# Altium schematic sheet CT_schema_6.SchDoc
size 368 x 245 mm
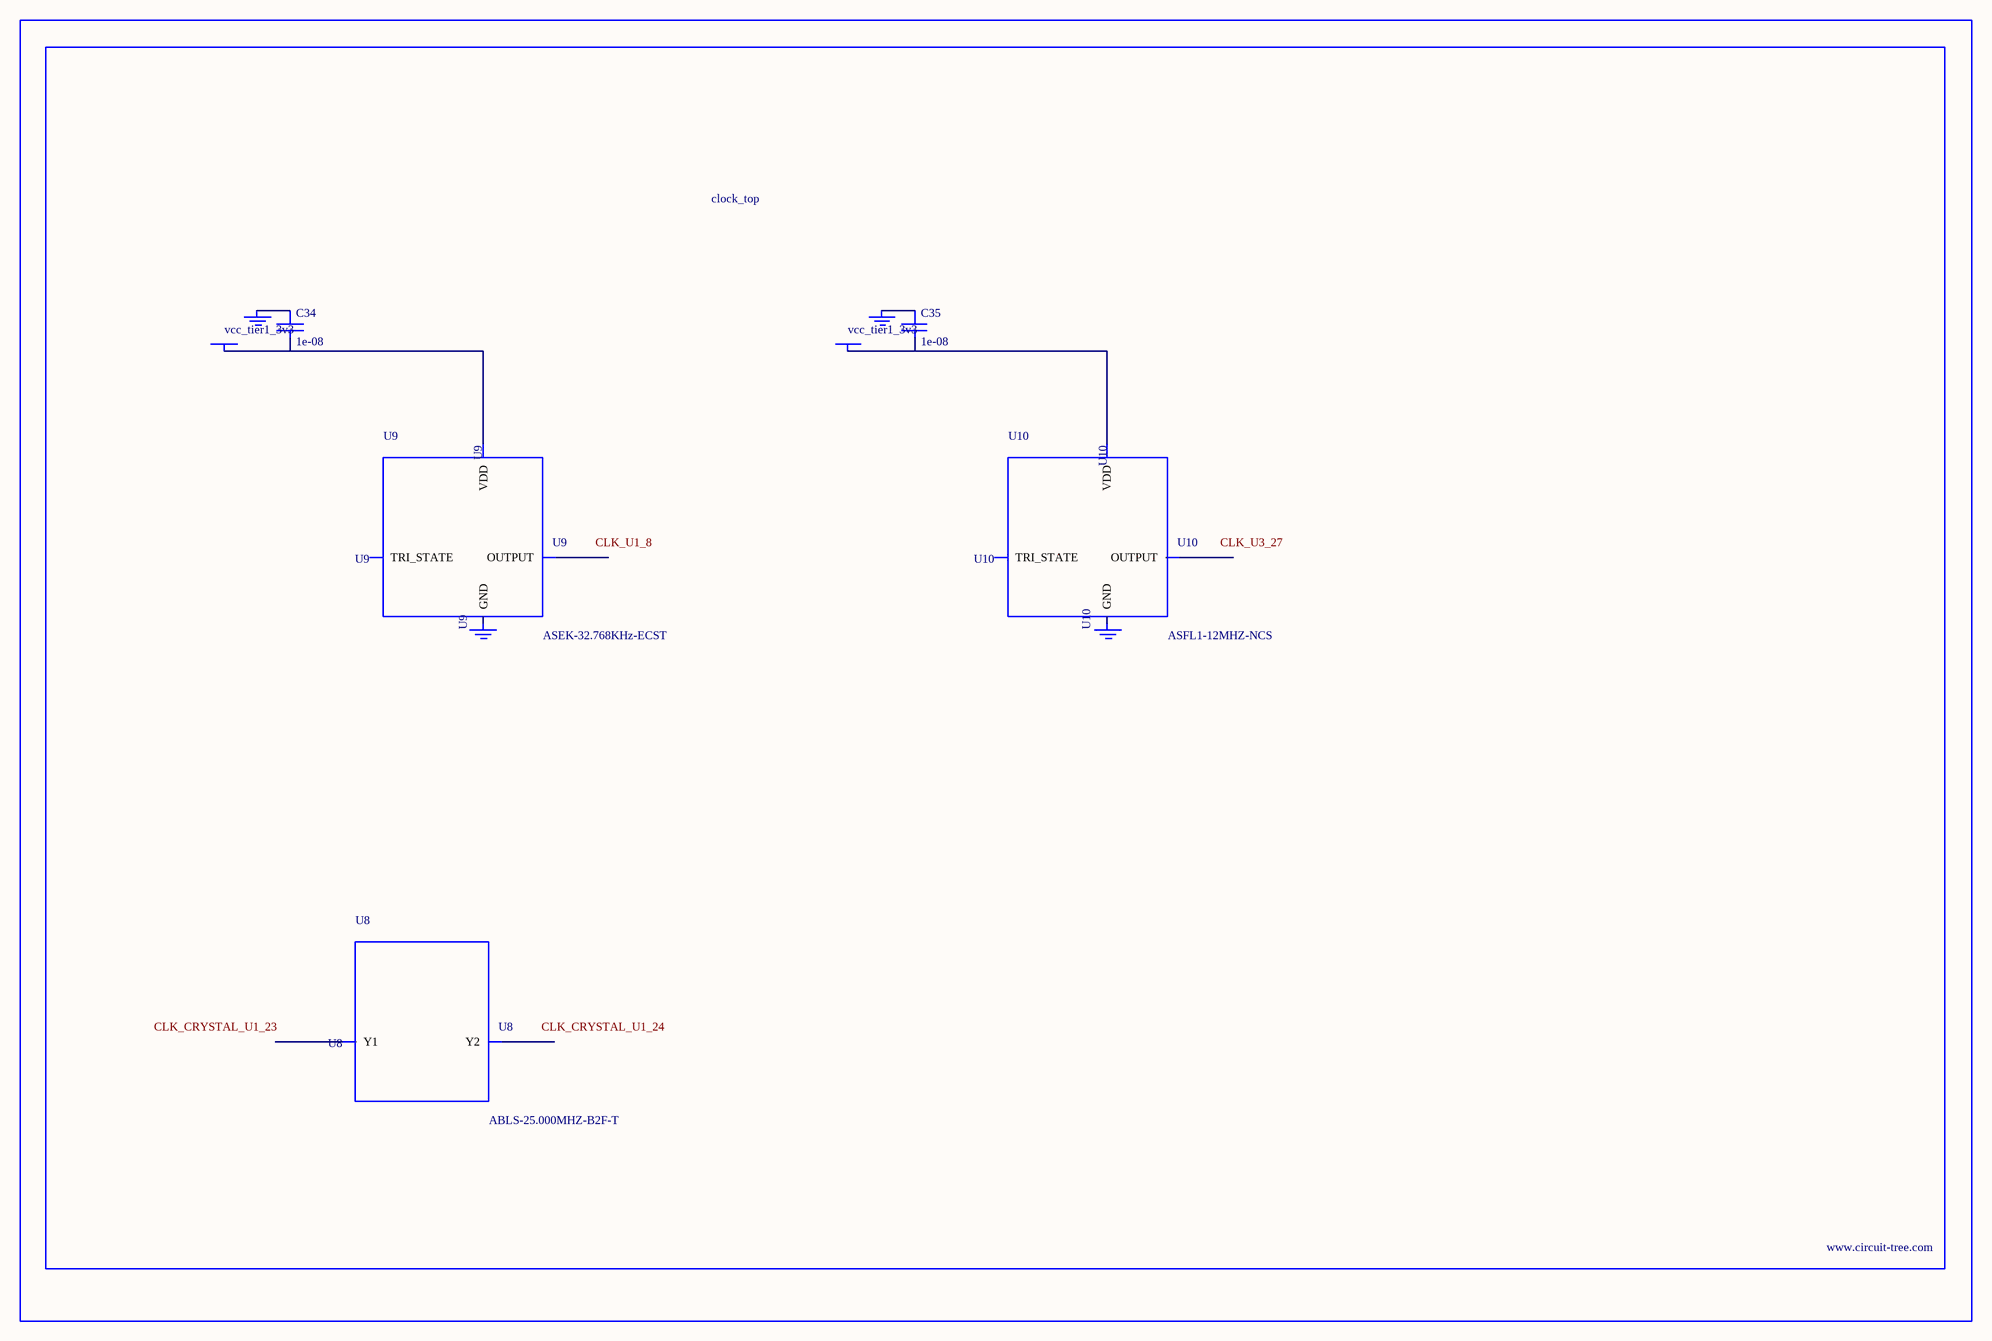
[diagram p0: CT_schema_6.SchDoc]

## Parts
BORDER5  (no value)
C34  1e-08  [C0402]
C35  1e-08  [C0402]
GND_INSTANCE_5_0  (no value)
GND_INSTANCE_5_1  (no value)
GND_INSTANCE_5_2  (no value)
GND_INSTANCE_5_3  (no value)
POWER_INSTANCE_5_0  vcc_tier1_3v3
POWER_INSTANCE_5_1  vcc_tier1_3v3
U8  ABLS-25.000MHZ-B2F-T  [ABLS-25.000MHZ-B2F-T]
U9  ASEK-32.768KHz-ECST  [ASEK]
U10  ASFL1-12MHZ-NCS  [ASFL1]

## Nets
NetC34_1: C34.1 GND_INSTANCE_5_0.0(GND)
NetC34_2: C34.2 POWER_INSTANCE_5_0.0(PWR) U9.4(VDD)
NetC35_1: C35.1 GND_INSTANCE_5_2.0(GND)
NetC35_2: C35.2 POWER_INSTANCE_5_1.0(PWR) U10.4(VDD)

Not connected (* = marked no-connect by the designer): GND_INSTANCE_5_1 0(GND); GND_INSTANCE_5_3 0(GND); U8 1(Y1) 2(Y2); U9 1(TRI_STATE) 2(GND) 3(OUTPUT); U10 1(TRI_STATE) 2(GND) 3(OUTPUT)

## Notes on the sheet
- Labels drawn without touching a wire or pin: CLK_CRYSTAL_U1_23, CLK_CRYSTAL_U1_24, CLK_U1_8, CLK_U3_27

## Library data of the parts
BORDER5 = BORDER_PAGE5
C34 C35 = C0402C103K3RAC
GND_INSTANCE_5_0-GND_INSTANCE_5_3 = GND
POWER_INSTANCE_5_0 POWER_INSTANCE_5_1 = PWR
